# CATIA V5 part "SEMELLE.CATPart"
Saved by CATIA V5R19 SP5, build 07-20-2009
Part number: SEMELLE
Bounding box of the stored display mesh (mm): x -31.5 to 31.5, y -210.881 to -130.881, z -2 to 35.463
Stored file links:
  C:\Documents and Settings\gilbert\Mes documents\Mon travail\travail 2011\IPM1\TP INDUS\SEANCE 13\MORS +MANDRIN TBI\SEMELLE.CATPart
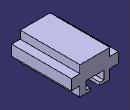
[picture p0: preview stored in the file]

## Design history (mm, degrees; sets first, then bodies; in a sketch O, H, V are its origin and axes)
Set1
  DatumCurve1 to DatumCurve6
  DatumPoint1
  DatumCurve7
Body1 (main body)
  Sketch1, origin (0, -130.881, 0), H (-1, 0, 0), V (0, 0, 1)
    line L1 (31.5, 11) -> (31.5, 25)
    line L2 (31.5, 25) -> (20, 25)
    line L3 (20, 25) -> (20, 35.4632)
    line L4 (20, 35.4632) -> (-20, 35.4632)
    line L5 (-20, 35.4632) -> (-20, 25)
    point P6 (-20, 25)
    line L6 (-20, 25) -> (-31.5, 25)
    line L7 (-31.5, 25) -> (-31.5, 11)
    line L8 (-31.5, 11) -> (-20, 11)
    point P9 (-20, 11)
    line L9 (-20, 11) -> (-20, -2)
    line L10 (-20, -2) -> (20, -2)
    point P11 (20, -2)
    line L11 (20, -2) -> (20, 11)
    point P12 (20, 11)
    line L12 (20, 11) -> (31.5, 11)
    reference projected line E1 (-20, 25) -> (-20, 38) from edge of DatumCurve1
    reference projected line E2 (20, 38) -> (20, 25) from edge of DatumCurve2
    reference projected line E3 (-20, 25) -> (-32.5, 25) from edge of DatumCurve3
    reference projected line E4 (-32.5, 11) -> (-20.8317, 11) from edge of DatumCurve4
    reference projected line E5 (-32.5, 11) -> (-32.5, 25) from edge of DatumCurve5
    reference projected line E6 (32.5, 25) -> (32.5, 11) from edge of DatumCurve6
    reference projected line E7 (-21, 0) -> (-103, 0) from edge of DatumCurve7
    distance L5 E1 = 0
    distance L3 E2 = 0
    distance L6 E3 = 0
    distance L8 E4 = 0
    distance L7 E5 = 1
    distance L1 E6 = 1
    distance L10 E7 = 2
    vertical: L1 V, L3 V, L5 V, L7 V, L9 V, L11 V
    horizontal: L2 H, L4 H, L6 H, L8 H, L10 H, L12 H
    coincidence: P6 L2, P9 L5, P11 L3, P12 L8
  Pad1: profile Sketch1, direction (0, -1, 0), length 80
  Sketch2 on start face of Pad1, origin (0, -130.881, 0), H (-1, 0, 0), V (0, 0, 1)
    line L1 (-6.5, -4) -> (-6.5, 2)
    line L2 (-6.5, 2) -> (-12, 2)
    line L3 (-12, 2) -> (-12, 13.0802)
    line L4 (-12, 13.0802) -> (12, 13.0802)
    line L5 (12, 13.0802) -> (12, 2)
    point P6 (12, 2)
    line L6 (12, 2) -> (6.5, 2)
    line L7 (6.5, 2) -> (6.5, -4)
    line L8 (6.5, -4) -> (-6.5, -4)
    reference projected line E1 (-20, -2) -> (20, -2) from edge [face of Pad1 from Sketch1.L10 | start face of Pad1]
    reference projected line E2 (-20, -2) -> (20, -2) from edge [face of Pad1 from Sketch1.L10 | start face of Pad1]
    length L8 = 13
    distance L7 V = 6.5
    distance L6 E1 = 4
    length L4 = 24
    distance L5 V = 12
    distance L8 E2 = 2
    vertical: L1 V, L3 V, L5 V, L7 V
    horizontal: L2 H, L4 H, L6 H, L8 H
    coincidence: P6 L2
  Pocket1: profile Sketch2, direction (0, -1, 0), through (limit type 6)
